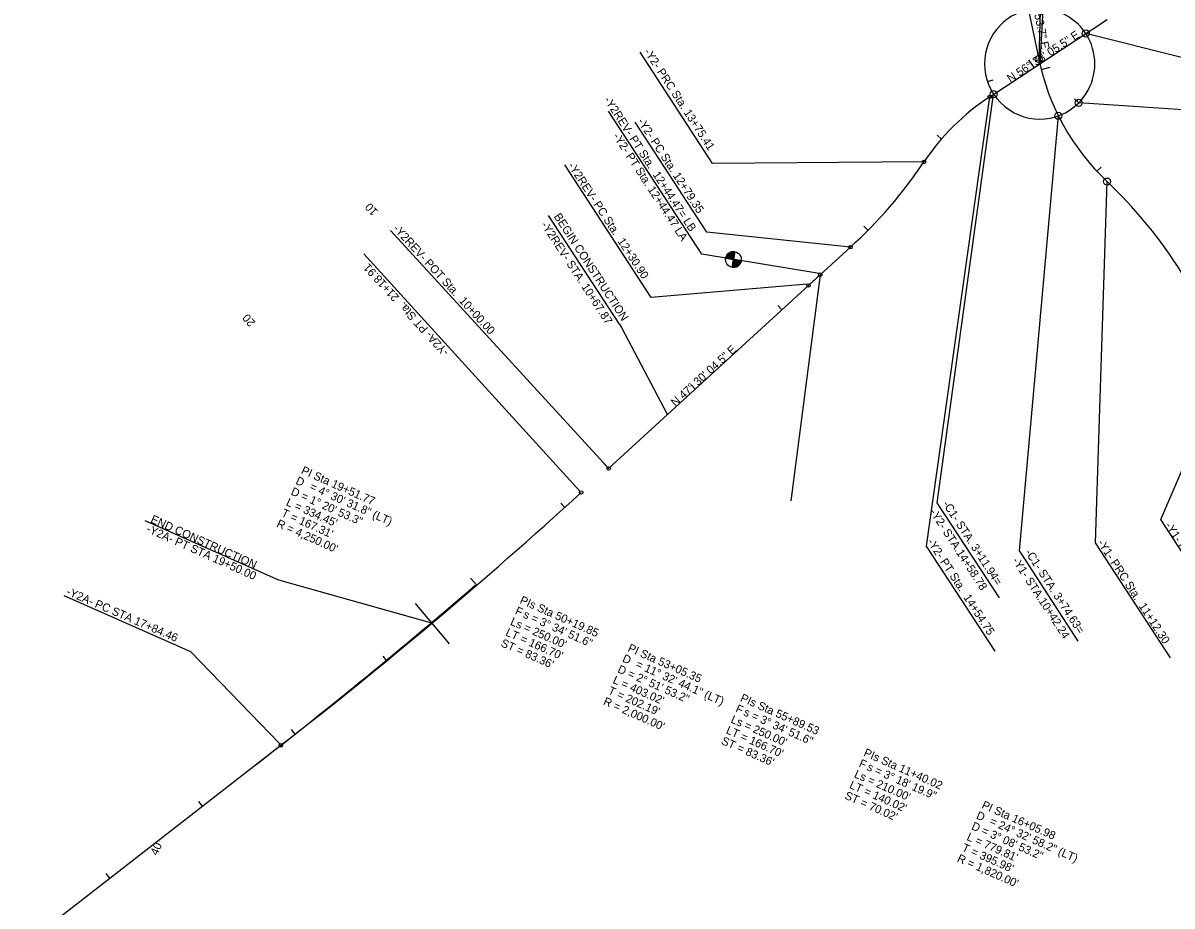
# Model space of a CAD drawing. Extents: x 1636713 to 1642889, y 841520 to 844630.
# Drawn here: x 1639512 to 1640491, y 843029 to 843782 of the extents above; entities that cross this region are included whole.
import ezdxf

# ---------------------------------------------------------------- set-up
doc = ezdxf.new("R2010")
doc.units = 0
for name, color, linetype in [('Exist 4 AWG with gnd feeder circuit in conduit', 7, 'Continuous'), ('Exist 6 AWG with gnd feeder circuit', 7, 'Continuous'), ('Exist 8 AWG with gnd feeder circuit', 7, 'Continuous'), ('Exist 8 AWG with gnd feeder circuit in conduit', 7, 'Continuous'), ('Prop 2 AWG with gnd feeder circuit', 7, 'Continuous'), ('Prop 2 AWG with gnd feeder circuit in conduit', 7, 'Continuous'), ('Prop 4 AWG with gnd feeder circuit', 7, 'Continuous'), ('Prop Berm Ditch Leader', 7, 'Continuous'), ('Prop Clearing and Grubbing', 7, 'Continuous'), ('Prop DSN Text', 7, 'Continuous')]:
    doc.layers.add(name, color=color, linetype=linetype)

msp = doc.modelspace()

# ---------------------------------------------------------------- linework, layer by layer
at = {"layer": 'Exist 6 AWG with gnd feeder circuit'}
for p, q in [((1640099.08, 843662.04), (1640037.4, 843756.67)), ((1640290.57, 843372.91), (1640338.54, 843720.94)), ((1640089.88, 843584.69), (1640010.36, 843706.55)), ((1640722.93, 843692.58), (1640411.03, 843713.56)), ((1640046.84, 843547.87), (1639973.13, 843660.84)), ((1640279.17, 843663.25), (1640099.08, 843662.04)), ((1640425.45, 843338.79), (1640435.18, 843646.55)), ((1640019.78, 843525.03), (1639959.33, 843617.65)), ((1640009.52, 843403.16), (1639824.75, 843604.81)), ((1639986.09, 843382.73), (1639801.89, 843584.9)), ((1639986.09, 843382.73), (1639801.89, 843584.9)), ((1640189.78, 843568.31), (1640089.88, 843584.69)), ((1640110.23, 843581.16), (1640116.86, 843580.09)), ((1640116.86, 843580.09), (1640110.23, 843581.16)), ((1640115.8, 843573.46), (1640116.86, 843580.09)), ((1640117.92, 843586.72), (1640116.86, 843580.09)), ((1640116.86, 843580.09), (1640123.49, 843579.03)), ((1640179.76, 843559.15), (1640046.84, 843547.87)), ((1640343.45, 843291.87), (1640290.57, 843372.91)), ((1640410.71, 843255.17), (1640362.46, 843329.11)), ((1639860.01, 843270.37), (1639729.64, 843306.87)), ((1639730.35, 843167.51), (1639654.5, 843246.01))]:
    msp.add_line(p, q, dxfattribs=at)
for points in [[(1640403.98, 844219.86), (1640377.83, 843746.81)], [(1640389.67, 844201.32), (1640376.95, 843750.85)], [(1640756.87, 843687.44), (1640417.05, 843772.64)], [(1640339.82, 843246.57), (1640281.42, 843336.07), (1640335.17, 843718.72)], [(1640216.58, 843590.69), (1640094.13, 843603.41), (1640032.98, 843697.24)], [(1640362.46, 843329.11), (1640360.64, 843331.91), (1640393.7, 843702.56)], [(1640116.87, 843580.19), (1640110.24, 843581.25), (1640110.24, 843581.25)], [(1640116.9, 843580.32), (1640110.27, 843581.38)], [(1640116.92, 843580.46), (1640110.3, 843581.51)], [(1640116.94, 843580.59), (1640110.32, 843581.65)], [(1640116.96, 843580.72), (1640110.36, 843581.78)], [(1640116.98, 843580.85), (1640110.4, 843581.91)], [(1640117, 843580.99), (1640110.43, 843582.04)], [(1640117.02, 843581.12), (1640110.48, 843582.17)], [(1640117.04, 843581.25), (1640110.52, 843582.3)], [(1640117.06, 843581.38), (1640110.57, 843582.42)], [(1640117.09, 843581.52), (1640110.62, 843582.55)], [(1640117.11, 843581.65), (1640110.67, 843582.68)], [(1640117.13, 843581.78), (1640110.72, 843582.81)], [(1640117.15, 843581.91), (1640110.79, 843582.93)], [(1640117.17, 843582.05), (1640110.84, 843583.06)], [(1640117.19, 843582.18), (1640110.9, 843583.19)], [(1640117.21, 843582.31), (1640110.97, 843583.31)], [(1640117.23, 843582.44), (1640111.03, 843583.44)], [(1640117.26, 843582.58), (1640111.11, 843583.56)], [(1640117.28, 843582.71), (1640111.19, 843583.68)], [(1640117.3, 843582.84), (1640111.27, 843583.81)], [(1640117.32, 843582.97), (1640111.35, 843583.93)], [(1640117.34, 843583.11), (1640111.43, 843584.05)], [(1640117.36, 843583.24), (1640111.53, 843584.17)], [(1640117.38, 843583.37), (1640111.62, 843584.29)], [(1640117.4, 843583.51), (1640111.72, 843584.42)], [(1640117.43, 843583.64), (1640111.83, 843584.53)], [(1640117.45, 843583.77), (1640111.94, 843584.65)], [(1640117.47, 843583.9), (1640112.05, 843584.77)], [(1640117.49, 843584.04), (1640112.16, 843584.89)], [(1640117.51, 843584.17), (1640112.28, 843585)], [(1640117.53, 843584.3), (1640112.41, 843585.12)], [(1640117.55, 843584.43), (1640112.54, 843585.23)], [(1640117.57, 843584.57), (1640112.68, 843585.35)], [(1640117.6, 843584.7), (1640112.82, 843585.46)], [(1640117.62, 843584.83), (1640112.98, 843585.57)], [(1640117.64, 843584.96), (1640113.15, 843585.68)], [(1640117.66, 843585.1), (1640113.31, 843585.79)], [(1640117.68, 843585.23), (1640113.5, 843585.9)], [(1640117.7, 843585.36), (1640113.68, 843586)], [(1640117.72, 843585.49), (1640113.88, 843586.11)], [(1640117.74, 843585.63), (1640114.09, 843586.21)], [(1640117.77, 843585.76), (1640114.32, 843586.31)], [(1640117.79, 843585.89), (1640114.58, 843586.41)], [(1640117.81, 843586.02), (1640114.85, 843586.5)], [(1640117.83, 843586.16), (1640115.15, 843586.59)], [(1640117.85, 843586.29), (1640115.48, 843586.67)], [(1640117.87, 843586.42), (1640115.9, 843586.74)], [(1640117.89, 843586.56), (1640116.39, 843586.8)], [(1640122.9, 843577.16), (1640116.55, 843578.17)], [(1640122.95, 843577.28), (1640116.57, 843578.31)], [(1640123.02, 843577.41), (1640116.59, 843578.44)], [(1640123.07, 843577.54), (1640116.61, 843578.57)], [(1640123.12, 843577.67), (1640116.64, 843578.7)], [(1640123.17, 843577.79), (1640116.66, 843578.84)], [(1640123.22, 843577.92), (1640116.68, 843578.97)], [(1640123.26, 843578.05), (1640116.7, 843579.1)], [(1640123.29, 843578.18), (1640116.72, 843579.23)], [(1640123.33, 843578.31), (1640116.74, 843579.37)], [(1640123.36, 843578.44), (1640116.76, 843579.5)], [(1640123.4, 843578.57), (1640116.78, 843579.63)], [(1640123.42, 843578.7), (1640116.81, 843579.76)], [(1640123.46, 843578.83), (1640116.83, 843579.9)], [(1640123.48, 843578.97), (1640123.48, 843578.97), (1640116.85, 843580.03)], [(1640117.91, 843586.69), (1640117.19, 843586.8)], [(1640116.75, 843573.38), (1640115.81, 843573.53)], [(1640117.45, 843573.4), (1640115.83, 843573.66)], [(1640117.93, 843573.46), (1640115.85, 843573.8)], [(1640118.32, 843573.54), (1640115.87, 843573.93)], [(1640118.65, 843573.62), (1640115.89, 843574.06)], [(1640118.95, 843573.71), (1640115.91, 843574.19)], [(1640119.21, 843573.8), (1640115.94, 843574.33)], [(1640119.45, 843573.9), (1640115.96, 843574.46)], [(1640119.68, 843574), (1640115.98, 843574.59)], [(1640119.89, 843574.1), (1640116, 843574.72)], [(1640120.09, 843574.21), (1640116.02, 843574.86)], [(1640120.27, 843574.31), (1640116.04, 843574.99)], [(1640120.45, 843574.42), (1640116.06, 843575.12)], [(1640120.62, 843574.53), (1640116.08, 843575.26)], [(1640120.78, 843574.64), (1640116.11, 843575.39)], [(1640120.93, 843574.75), (1640116.13, 843575.52)], [(1640121.07, 843574.87), (1640116.15, 843575.65)], [(1640121.21, 843574.98), (1640116.17, 843575.79)], [(1640121.35, 843575.09), (1640116.19, 843575.92)], [(1640121.47, 843575.21), (1640116.21, 843576.05)], [(1640121.58, 843575.33), (1640116.23, 843576.18)], [(1640121.7, 843575.44), (1640116.25, 843576.32)], [(1640121.81, 843575.56), (1640116.28, 843576.45)], [(1640121.92, 843575.68), (1640116.3, 843576.58)], [(1640122.02, 843575.8), (1640116.32, 843576.71)], [(1640122.11, 843575.92), (1640116.34, 843576.85)], [(1640122.21, 843576.04), (1640116.36, 843576.98)], [(1640122.3, 843576.16), (1640116.38, 843577.11)], [(1640122.38, 843576.29), (1640116.4, 843577.24)], [(1640122.46, 843576.41), (1640116.42, 843577.38)], [(1640122.54, 843576.53), (1640116.44, 843577.51)], [(1640122.62, 843576.66), (1640116.47, 843577.64)], [(1640122.7, 843576.78), (1640116.49, 843577.77)], [(1640122.77, 843576.91), (1640116.51, 843577.91)], [(1640122.84, 843577.03), (1640116.53, 843578.04)], [(1640019.78, 843525.03), (1640021.58, 843522.26), (1640060.25, 843448.26)], [(1640542.47, 843264.37), (1640480.93, 843358.68), (1640537.16, 843489.66)], [(1639729.64, 843306.87), (1639615.61, 843357.51)], [(1640489.32, 843240.92), (1640425.45, 843338.79)], [(1639654.5, 843246.01), (1639546.71, 843293.7)]]:
    msp.add_lwpolyline(points, dxfattribs=at)
for centre, radius in [((1640417.05, 843772.64), 3), ((1640376.95, 843750.85), 3), ((1640335.17, 843718.72), 1.5), ((1640338.54, 843720.94), 3), ((1640411.03, 843713.56), 3), ((1640393.7, 843702.56), 3), ((1640279.17, 843663.25), 1.5), ((1640435.18, 843646.55), 3), ((1640216.58, 843590.69), 1.5), ((1640116.86, 843580.09), 6.71), ((1640190.79, 843567.2), 1.5), ((1640180.77, 843558.04), 1.5), ((1640010.54, 843402.06), 1.5), ((1639987.1, 843381.62), 1.5), ((1639987.1, 843381.62), 1.5), ((1639731.27, 843166.33), 1.5)]:
    msp.add_circle(centre, radius, dxfattribs=at)
for start, end in [(80.89771, 170.89771), (260.89771, 350.89771)]:
    msp.add_arc((1640116.86, 843580.09), 6.71, start, end, dxfattribs=at)
at = {"layer": 'Exist 8 AWG with gnd feeder circuit'}
for p, q in [((1640361.94, 843822.7), (1640376.95, 843750.85)), ((1640335.17, 843718.72), (1640435.28, 843784.64)), ((1640190.79, 843567.2), (1640216.58, 843590.69)), ((1640010.54, 843402.06), (1640180.77, 843558.04)), ((1639225.26, 842773.45), (1639731.27, 843166.33))]:
    msp.add_line(p, q, dxfattribs=at)
for centre, radius, start, end in [((1640377.79, 843746.79), 47, 20.39794, 135), ((1640377.79, 843746.79), 47, 135, 225), ((1640377.79, 843746.79), 47, 315, 20.39794), ((1640572.72, 843791.74), 200, 191.79824, 226.55094), ((1640445.17, 843551.69), 200, 123.36513, 146.09565), ((1640377.79, 843746.79), 47, 225, 315), ((1639947.19, 843886.37), 400, 312.33575, 326.09565), ((1640160.09, 843356.15), 400, 19.49801, 46.55094), ((1643403.26, 840041.16), 4770, 132.33575, 132.49875), ((1637124.83, 846523.26), 4250, 307.82692, 312.33575)]:
    msp.add_arc(centre, radius, start, end, dxfattribs=at)
at = {"layer": 'Prop 2 AWG with gnd feeder circuit in conduit'}
for p, q in [((1640372.96, 843743.61), (1640368.56, 843750.29)), ((1640378.98, 843742.08), (1640386.73, 843744.06)), ((1640010.54, 843402.06), (1640005.13, 843407.96)), ((1639898.09, 843302.77), (1639892.87, 843308.84))]:
    msp.add_line(p, q, dxfattribs=at)
at = {"layer": 'Prop 4 AWG with gnd feeder circuit'}
for p, q in [((1640333.3, 843731.63), (1640338.04, 843733.25)), ((1640411.03, 843713.56), (1640407.49, 843717.09)), ((1640294.11, 843682.77), (1640290.33, 843686.04)), ((1640426.51, 843655.28), (1640430.17, 843658.69)), ((1640231.48, 843604.99), (1640227.92, 843608.5)), ((1640158, 843537.17), (1640154.62, 843540.86)), ((1640084.27, 843469.61), (1640080.89, 843473.3)), ((1639973.09, 843368.91), (1639969.74, 843372.62)), ((1639821.55, 843238.42), (1639818.38, 843242.28)), ((1639743.52, 843175.88), (1639740.44, 843179.82)), ((1639664.55, 843114.53), (1639661.49, 843118.48)), ((1639585.57, 843053.2), (1639582.5, 843057.15))]:
    msp.add_line(p, q, dxfattribs=at)
at = {"layer": 'Prop Berm Ditch Leader'}
msp.add_line((1639111.65, 842685.24), (1639731.27, 843166.33), dxfattribs=at)
msp.add_arc((1637124.83, 846523.26), 4250, 307.82692, 312.33575, dxfattribs=at)
at = {"layer": 'Prop Clearing and Grubbing'}
for p, q in [((1640190.79, 843567.2), (1640165.8, 843374.65)), ((1640010.54, 843402.06), (1640180.77, 843558.04)), ((1640060.25, 843448.26), (1640060.58, 843447.91))]:
    msp.add_line(p, q, dxfattribs=at)
for centre, start, end in [((1643403.26, 840041.16), 132.33575, 132.49875), ((1636784.75, 846917.55), 307.82692, 310.72535)]:
    msp.add_arc(centre, 4770, start, end, dxfattribs=at)
at = {"layer": 'Prop DSN Text'}
msp.add_line((1639874.8, 843252.78), (1639845.93, 843287.11), dxfattribs=at)

# ---------------------------------------------------------------- texts
at = {"layer": 'Exist 4 AWG with gnd feeder circuit in conduit'}
for s, rotation, p in [('10', 132.49875, (1639814.4, 843621.29)), ('20', 130.73268, (1639709.96, 843526.61)), ('40', 66.08714, (1639626.03, 843072.06))]:
    msp.add_text(s, height=7, rotation=rotation, dxfattribs=at).set_placement(p)
at = {"layer": 'Exist 6 AWG with gnd feeder circuit'}
for s, rotation, p in [('-Y2- PRC Sta. 13+75.41', 303.12591, (1640040.31, 843757.12)), ('-Y2REV- PT Sta.  12+44.47= LB', 303.12591, (1640006.24, 843716.04)), ('-Y2- PC Sta. 12+79.35', 303.12591, (1640034.82, 843697.81)), ('-Y2- PT Sta. 12+44.47 LA', 303.12591, (1640013.86, 843685.15)), ('-Y2REV- PC Sta.  12+30.90', 303.28892, (1639975.52, 843660.08)), ('BEGIN CONSTRUCTION', 303.12591, (1639963.49, 843616.78)), ('-Y2REV- POT Sta.  10+00.00', 312.49875, (1639826.44, 843605.93)), ('-Y2REV- STA. 10+67.87', 303.12591, (1639952.6, 843609.68)), ('-Y2A- PT Sta.  21+18.91', 132.33575, (1639874.94, 843501.76)), ('-C1- STA. 3+11.94=', 303.12591, (1640294.72, 843372.04)), ('-Y2- STA.14+58.78', 303.12591, (1640283.83, 843364.93)), ('-Y2A- PT STA 19+50.00', 335.85363, (1639615.99, 843348.35)), ('END CONSTRUCTION', 335.85363, (1639619.62, 843356.45)), ('-Y1- PRC Sta.  13+01.17', 303.12591, (1640484.17, 843353.72)), ('-Y2- PT Sta.  14+54.75', 303.12591, (1640281.59, 843339.75)), ('-Y1- PRC Sta.  11+12.30', 303.12591, (1640426.66, 843338.95)), ('-Y1- STA.10+42.24', 303.12591, (1640354.09, 843323.64)), ('-C1- STA. 3+74.63=', 303.12591, (1640364.98, 843330.74)), ('-Y2A- PC STA 17+84.46', 336.59915, (1639547.82, 843294.83))]:
    msp.add_text(s, height=7, rotation=rotation, dxfattribs=at).set_placement(p)
at = {"layer": 'Exist 8 AWG with gnd feeder circuit in conduit'}
for s, rotation, p in [('S 11%%d 47\' 53.7" E', 281.79824, (1640364.85, 843828.28)), ('N 56%%d 38\' 05.5" E', 33.36513, (1640352.81, 843730.58)), ('N 47%%d 30\' 04.5" E', 42.49875, (1640067.45, 843454.47))]:
    msp.add_text(s, height=7, rotation=rotation, dxfattribs=at).set_placement(p)
at = {"layer": 'Prop 2 AWG with gnd feeder circuit'}
for s, rotation, p in [('PI Sta 19+51.77', 335.96803, (1639747.97, 843398.07)), ('D', 335.96803, (1639743.28, 843389.21)), ('D = 1%%d 20\' 53.3"', 335.96803, (1639739.21, 843380.08)), ('= 4%%d 30\' 31.8" (LT)', 335.96803, (1639755.13, 843384.25)), ("L = 334.45'", 335.96803, (1639735.13, 843370.94)), ("T = 167.31'", 335.96803, (1639731.06, 843361.81)), ("R = 4,250.00'", 335.96803, (1639726.99, 843352.68)), ('F', 336.08714, (1639930.2, 843278.39)), ('PIs Sta 50+19.85', 336.08714, (1639934.26, 843287.53)), ("Ls = 250.00'", 336.08714, (1639926.15, 843269.25)), ('s = 3%%d 34\' 51.6"', 336.08714, (1639937.07, 843275.35)), ("LT = 166.70'", 336.08714, (1639922.1, 843260.11)), ("ST = 83.36'", 336.08714, (1639918.04, 843250.97)), ('PI Sta 53+05.35', 336.08714, (1640026.26, 843246.74)), ('D', 336.08714, (1640021.59, 843237.87)), ('= 11%%d 32\' 44.1" (LT)', 336.08714, (1640032.98, 843232.95)), ("L = 403.02'", 336.08714, (1640013.48, 843219.59)), ('D = 2%%d 51\' 53.2"', 336.08714, (1640017.54, 843228.73)), ("T = 202.19'", 336.08714, (1640009.43, 843210.45)), ("R = 2,000.00'", 336.08714, (1640005.37, 843201.31)), ('PIs Sta 55+89.53', 336.08714, (1640122.11, 843204.24)), ('F', 336.08714, (1640118.05, 843195.1)), ('s = 3%%d 34\' 51.6"', 336.08714, (1640124.92, 843192.05)), ("Ls = 250.00'", 336.08714, (1640114, 843185.96)), ("LT = 166.70'", 336.08714, (1640109.94, 843176.82)), ("ST = 83.36'", 336.08714, (1640105.89, 843167.67)), ('PIs Sta 11+40.02', 336.08714, (1640227.21, 843157.63)), ('F', 336.08714, (1640223.16, 843148.49)), ('s = 3%%d 18\' 19.9"', 336.08714, (1640230.03, 843145.45)), ("Ls = 210.00'", 336.08714, (1640219.11, 843139.35)), ("LT = 140.02'", 336.08714, (1640215.05, 843130.21)), ("ST = 70.02'", 336.08714, (1640211, 843121.07)), ('PI Sta 16+05.98', 336.08714, (1640327.77, 843113.05)), ('D', 336.08714, (1640323.1, 843104.18)), ('D = 3%%d 08\' 53.2"', 336.08714, (1640319.05, 843095.04)), ('= 24%%d 32\' 58.2" (LT)', 336.08714, (1640334.49, 843099.26)), ("L = 779.81'", 336.08714, (1640315, 843085.9)), ("T = 395.98'", 336.08714, (1640310.94, 843076.75)), ("R = 1,820.00'", 336.08714, (1640306.89, 843067.61))]:
    msp.add_text(s, height=7, rotation=rotation, dxfattribs=at).set_placement(p)

doc.saveas('drawing.dxf')
